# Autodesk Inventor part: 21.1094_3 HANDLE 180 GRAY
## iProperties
Created: 2007-03
Part Number: 21.1094_3 HANDLE 180 GRAY
Document SubType Name: Modeling
Designer: Andy Moles
Material: ABS Plastic
Density: 1.06 g/cm^3
Mass: 60.9279 g
Surface Area: 218.997 cm^2
Volume: 57.4792 cm^3
Author: Andy Moles
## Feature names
1. Extrusion1
2. Extrusion2
3. Extrusion3
4. Extrusion4
5. Fillet1
6. Fillet2
7. Fillet3
